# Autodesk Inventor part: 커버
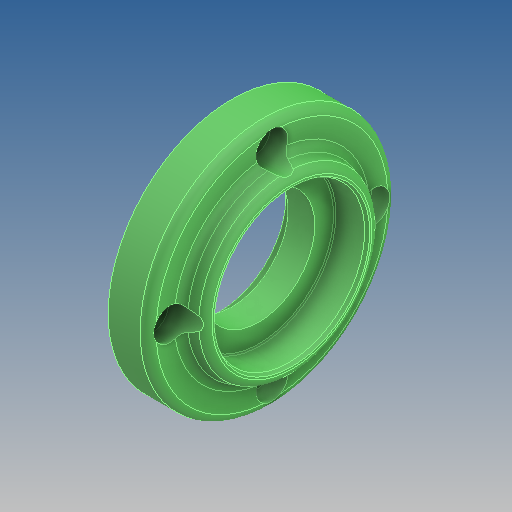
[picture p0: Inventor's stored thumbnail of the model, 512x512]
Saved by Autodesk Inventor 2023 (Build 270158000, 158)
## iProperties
Created: 2025-03
Part Number: 커버
Material: 알루미늄 6061
Document SubType Name: Modeling
Designer: Admin
Density: 2.71 g/cm^3
Appearance: 기본값
Author: jhkim
Sending System: Autodesk Inventor 2025
Preprocessor: ST-DEVELOPER v20
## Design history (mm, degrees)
node "커버1"
node "솔리드2"
node "솔리드1"
